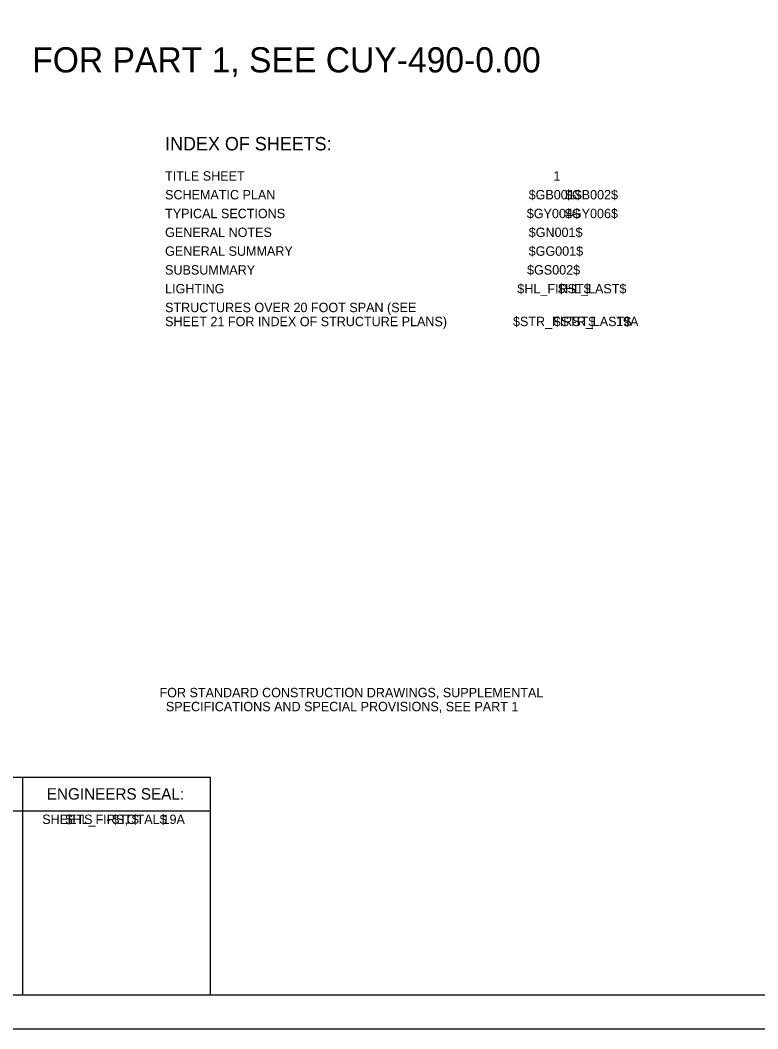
# Model space of a CAD drawing. Extents: x 0 to 96.2, y -27.5 to 31.3.
# Drawn here: x 53.23 to 64.23, y -0.11 to 14.92 of the extents above; entities that cross this region are included whole.
import ezdxf

# ---------------------------------------------------------------- set-up
doc = ezdxf.new("R2010")
doc.units = 0
for name, color, linetype in [('DIM', 7, 'Continuous'), ('TB1', 7, 'Continuous'), ('text', 7, 'Continuous')]:
    doc.layers.add(name, color=color, linetype=linetype)

msp = doc.modelspace()

# ---------------------------------------------------------------- linework, layer by layer
at = {"layer": 'DIM'}
msp.add_lwpolyline([(43.223, 21.387), (74.723, 21.387), (74.723, 0.387), (43.223, 0.387)], close=True, dxfattribs=at)
at = {"layer": 'TB1'}
for p, q in [((50.473, 3.637), (53.273, 3.637)), ((53.273, 0.387), (53.273, 3.637)), ((53.273, 0.387), (53.273, 3.637)), ((53.273, 3.637), (56.073, 3.637)), ((56.073, 0.387), (56.073, 3.637)), ((50.473, 3.137), (53.273, 3.137)), ((53.273, 3.137), (56.073, 3.137))]:
    msp.add_line(p, q, dxfattribs=at)
at = {"layer": 'text'}
msp.add_lwpolyline([(41.223, -0.113), (75.223, -0.113), (75.223, 21.887), (41.223, 21.887)], close=True, dxfattribs=at)

# ---------------------------------------------------------------- texts
at = {"layer": 'TB1'}
for s, height, p in [('FOR PART 1, SEE CUY-490-0.00', 0.375, (53.413, 14.137)), ('INDEX OF SHEETS:', 0.2, (55.394, 12.975)), ('TITLE SHEET', 0.14, (55.394, 12.525)), ('1', 0.14, (61.182, 12.525)), ('SCHEMATIC PLAN', 0.14, (55.394, 12.245)), ('$GB001$', 0.14, (60.813, 12.245)), ('$GB002$', 0.14, (61.354, 12.245)), ('-', 0.14, (61.458, 12.245)), ('TYPICAL SECTIONS', 0.14, (55.394, 11.965)), ('$GY004$', 0.14, (60.785, 11.965)), ('$GY006$', 0.14, (61.353, 11.965)), ('-', 0.14, (61.458, 11.965)), ('GENERAL NOTES', 0.14, (55.394, 11.685)), ('$GN001$', 0.14, (60.814, 11.685)), ('GENERAL SUMMARY', 0.14, (55.394, 11.405)), ('$GG001$', 0.14, (60.813, 11.405)), ('$GS002$', 0.14, (60.789, 11.125)), ('SUBSUMMARY', 0.14, (55.394, 11.125)), ('LIGHTING', 0.14, (55.394, 10.845)), ('$HL_FIRST$', 0.14, (60.644, 10.845)), ('$HL_LAST$', 0.14, (61.25, 10.845)), ('-', 0.14, (61.458, 10.845)), ('STRUCTURES OVER 20 FOOT SPAN (SEE ', 0.14, (55.394, 10.565)), ('SHEET 21 FOR INDEX OF STRUCTURE PLANS)', 0.14, (55.394, 10.356)), ('$STR_FIRST$', 0.14, (60.579, 10.357)), ('$STR_LAST$', 0.14, (61.186, 10.357)), ('-    ,', 0.14, (61.465, 10.357)), ('19A', 0.14, (62.116, 10.357)), ('FOR STANDARD CONSTRUCTION DRAWINGS, SUPPLEMENTAL', 0.14, (55.311, 4.827)), ('SPECIFICATIONS AND SPECIAL PROVISIONS, SEE PART 1', 0.14, (55.406, 4.619)), ('ENGINEERS SEAL:', 0.17, (53.631, 3.302)), ('SHEETS    -    ,', 0.14, (53.563, 2.939)), ('$HL_FIRST$', 0.14, (53.909, 2.939)), ('$TOTAL$', 0.14, (54.605, 2.939)), ('19A', 0.14, (55.356, 2.939))]:
    msp.add_text(s, height=height, dxfattribs=at).set_placement(p)

doc.saveas('drawing.dxf')
